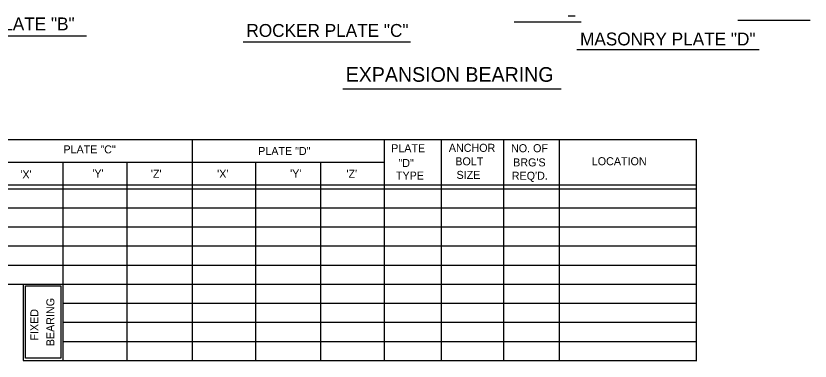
# Model space of a CAD drawing. Extents: x -1.11 to 1.92, y -1.37 to 1.11.
# Drawn here: x -0.387 to 0.643, y -0.042 to 0.406 of the extents above; entities that cross this region are included whole.
import ezdxf

# ---------------------------------------------------------------- set-up
doc = ezdxf.new("R2010")
doc.units = 0
doc.layers.add('Level 2', color=7, linetype='Continuous')

msp = doc.modelspace()

# ---------------------------------------------------------------- linework, layer by layer
at = {"layer": 'Level 2'}
for p, q in [((0.3293, 0.4063), (0.3384, 0.4063)), ((0.3459, 0.3982), (0.259, 0.3982)), ((0.643, 0.4005), (0.5494, 0.4005)), ((-0.4644, 0.3805), (-0.2958, 0.3805)), ((-0.0925, 0.3726), (0.1246, 0.3726)), ((0.3404, 0.3625), (0.5769, 0.3625)), ((0.0368, 0.3115), (0.3201, 0.3115)), ((-0.7998, 0.246), (0.496, 0.246)), ((-0.1587, 0.246), (-0.1587, -0.0416)), ((0.0903, 0.246), (0.0903, -0.0416)), ((0.1646, 0.246), (0.1646, -0.0416)), ((0.2451, 0.246), (0.2451, -0.0416)), ((0.3173, 0.246), (0.3173, -0.0416)), ((0.4953, 0.246), (0.4953, -0.0416)), ((-0.7468, 0.2164), (0.0903, 0.2164)), ((-0.3263, 0.2164), (-0.3263, -0.0407)), ((-0.2431, 0.2164), (-0.2431, -0.0416)), ((-0.0764, 0.2164), (-0.0764, -0.0416)), ((0.008, 0.2164), (0.008, -0.0416)), ((-0.7998, 0.1869), (0.496, 0.1869)), ((-0.7468, 0.182), (0.496, 0.182)), ((-0.7468, 0.1573), (0.4953, 0.1573)), ((-0.7468, 0.1325), (0.496, 0.1325)), ((-0.7468, 0.1078), (0.4953, 0.1078)), ((-0.7468, 0.083), (0.496, 0.083)), ((-0.7998, 0.0583), (0.4953, 0.0583)), ((-0.3776, 0.0583), (-0.3776, -0.0407)), ((-0.3263, 0.0335), (0.496, 0.0335)), ((-0.3263, 0.0088), (0.496, 0.0088)), ((-0.3263, -0.016), (0.496, -0.016)), ((-0.3776, -0.0407), (0.496, -0.0407))]:
    msp.add_line(p, q, dxfattribs=at)
msp.add_lwpolyline([(-0.3289, -0.0378), (-0.3748, -0.0378), (-0.3748, 0.0562), (-0.3289, 0.0562)], close=True, dxfattribs=at)

# ---------------------------------------------------------------- texts
for s, height, p in [('ON PLATE "B"', 0.016667, (-0.4581, 0.3876)), ('ROCKER PLATE "C"', 0.016667, (-0.0882, 0.3791)), ('MASONRY PLATE "D"', 0.016667, (0.3446, 0.368)), ('EXPANSION BEARING', 0.019, (0.0406, 0.3208)), ('PLATE "C"', 0.0104, (-0.3255, 0.2279)), ('PLATE', 0.0104, (0.0996, 0.2294)), ('ANCHOR', 0.0104, (0.1744, 0.2299)), ('NO. OF', 0.0104, (0.2551, 0.2294)), ('PLATE "D"', 0.0104, (-0.0729, 0.2258)), (' "D"', 0.0104, (0.1052, 0.2102)), ('BOLT', 0.0104, (0.1828, 0.2124)), ("BRG'S", 0.01042, (0.2578, 0.211)), ('LOCATION', 0.01042, (0.3598, 0.2125)), ("'Y'", 0.0104, (-0.288, 0.1966)), ("'Z'", 0.0104, (-0.2121, 0.1962)), ("'X'", 0.0104, (-0.1261, 0.1962)), ("'Y'", 0.0104, (-0.0315, 0.1966)), ("'Z'", 0.0104, (0.0416, 0.1962)), ("'X'", 0.0104, (-0.3814, 0.1954)), ('TYPE', 0.0104, (0.1058, 0.1939)), ('SIZE', 0.0104, (0.1844, 0.1948)), ("REQ'D.", 0.0104, (0.2561, 0.1937))]:
    msp.add_text(s, height=height, dxfattribs=at).set_placement(p)
for s, p in [('BEARING', (-0.3373, -0.0223)), ('FIXED', (-0.3581, -0.015))]:
    msp.add_text(s, height=0.0104, rotation=90, dxfattribs=at).set_placement(p)

doc.saveas('drawing.dxf')
